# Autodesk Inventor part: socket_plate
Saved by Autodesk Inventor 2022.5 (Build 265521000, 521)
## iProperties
Created: 2024-12
Part Number: socket_plate
Material: Generic
Document SubType Name: Modeling
Designer: AdminForWorker
Density: 1 g/cm^3
Appearance: Default
Title: socket_plate
Author: AdminForWorker
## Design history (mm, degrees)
feature "Body1"
body "Solid1"
